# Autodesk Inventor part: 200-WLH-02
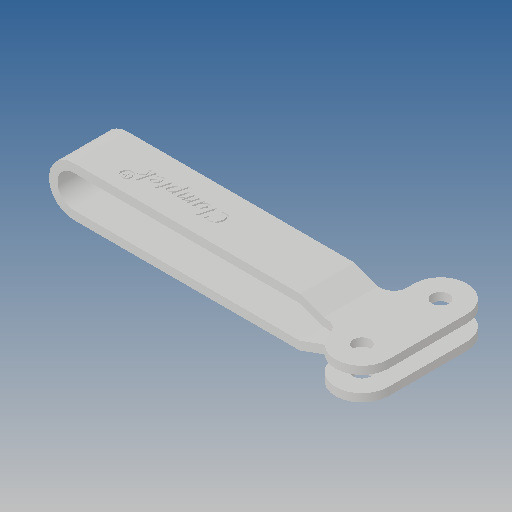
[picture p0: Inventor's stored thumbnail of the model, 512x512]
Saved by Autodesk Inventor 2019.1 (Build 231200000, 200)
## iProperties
Created: 2011-05
Part Number: 200-WLH-02
Material: Ogólny
Document SubType Name: Modeling
Designer: CADENGINEERING4
Density: 1 g/cm^3
Appearance: Domyślna
Author: CADENGINEERING4
Revision Number: ÈÎºÎ
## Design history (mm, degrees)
feature "ÇÐ³ý-À­Éì4"
node "Bryła1"
